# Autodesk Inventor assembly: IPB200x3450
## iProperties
Created: 2008-03
Part Number: IPB200x3450
Document SubType Name: Assembly
Designer: bts
Mass: 211464 g
Surface Area: 39869 cm^2
Volume: 26938.1 cm^3
Density: 7.85 g/cm^3
Author: bts
